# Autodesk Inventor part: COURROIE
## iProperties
Created: 2004-11
Part Number: COURROIE
Document SubType Name: Modeling
Designer: Bruno
Manufacturer: Standard
Standards Organization: Custom
Author: Bruno
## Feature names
1. Base1
